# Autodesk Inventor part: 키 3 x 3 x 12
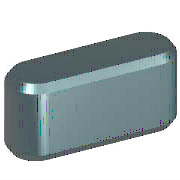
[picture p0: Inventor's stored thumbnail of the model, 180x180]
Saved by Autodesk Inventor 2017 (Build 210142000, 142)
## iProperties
Created: 2012-02
Part Number: 키 3 x 3 x 12
Material: 강철, 연강
Description: 키 및 해당 키홈
Document SubType Name: Modeling
Standard: KS B 1311
Designer: mduedu
Standards Organization: KS
Language: ko-KR
Size Designation: 3 x 3 x 12
Categories: <MemberInstance><Categories><Category DisplayName="샤프트 부품" InternalName="7f7aeb1f-a693-4053-b835-cee3144e0d98" Mnemonic="SHFT"><Category DisplayName="키" Interna
Density: 1 g/cm^3
Appearance: 노란색
IsCustomPart: 1
Author: mduedu
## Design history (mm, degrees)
workplane "Work Plane1"
workplane "Work Plane2"
sketch "스케치1"
  geometry: L1 (1.5, 1.5)-(10.5, 1.5); L2 (10.5, -1.5)-(1.5, -1.5); L3 (0, 9.4)-(0, -7.4) reference; L4 (-5, 0)-(30, 0) reference; L5 (12, 0)-(12, 7); A1 r 1.5 centre (1.5, 0) between (1.5, 1.5) and (1.5, -1.5); A2 r 1.5 centre (10.5, 0) between (10.5, -1.5) and (10.5, 1.5)
  constraints: 6 end point, 5 point on circle, 4 tangent, 3 point on line, 2 centre point, 1 horizontal, 1 parallel, 1 perpendicular
  dimensions: "d0" = 1.5 radius of A1 (= 0.5 x PB); "d13" = 1.5 radius of A2 (= 0.5 x PB); "d14" = 12 distance between parallel lines of L5 L3 (= NLG)
extrude "본체1" new body sketch "스케치1" taper "d3" = 0 deg; stored distance "d4" = 10
workplane "Work Plane3"
body "Solid1"
chamfer "모따기1" distance "d8" = 0.25 (= PHH); stored, may be unused: second distance "d9" = 0.25 (= PHH), angle "d15" = 45 deg
other parameters: "d1" = -1.8 (= -PNT), "d2" = 1.2 (= PH - PNT), "NLG" = 12 [user parameter; used in 3 equation terms], "PB" = 3 [user parameter; used in 2 equation terms], "PNT" = 1.8 [user parameter; used in 2 equation terms], "PH" = 3 [user parameter; used in 1 equation term], "PHH" = 0.25 [user parameter; used in 2 equation terms], "d10" = 0, "d16" = 0, "d17" = 0, "d18" = 0, "WDMIN" = 8 [user parameter], "PLB2" = 12 (= NLG) [user parameter], "PLB1" = 12 (= NLG) [user parameter], "RR" = 0.08 [user parameter], "PUEB" = 1.4 [user parameter]
